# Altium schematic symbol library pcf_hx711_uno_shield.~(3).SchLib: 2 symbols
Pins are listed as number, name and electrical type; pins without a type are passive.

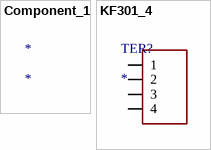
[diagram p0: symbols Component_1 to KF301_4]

## Component_1
designator *

## KF301_4
designator TER?
footprint KF304_4
pins: 1, 2, 3, 4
